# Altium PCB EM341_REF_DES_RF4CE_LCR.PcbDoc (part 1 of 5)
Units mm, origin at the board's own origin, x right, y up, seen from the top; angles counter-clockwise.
Board outline 218.38 x 83.13 mm, 2 copper layers (Top Layer, Carbon Ink Layer); 111 components, 91 nets, 369 pads, 80 vias.
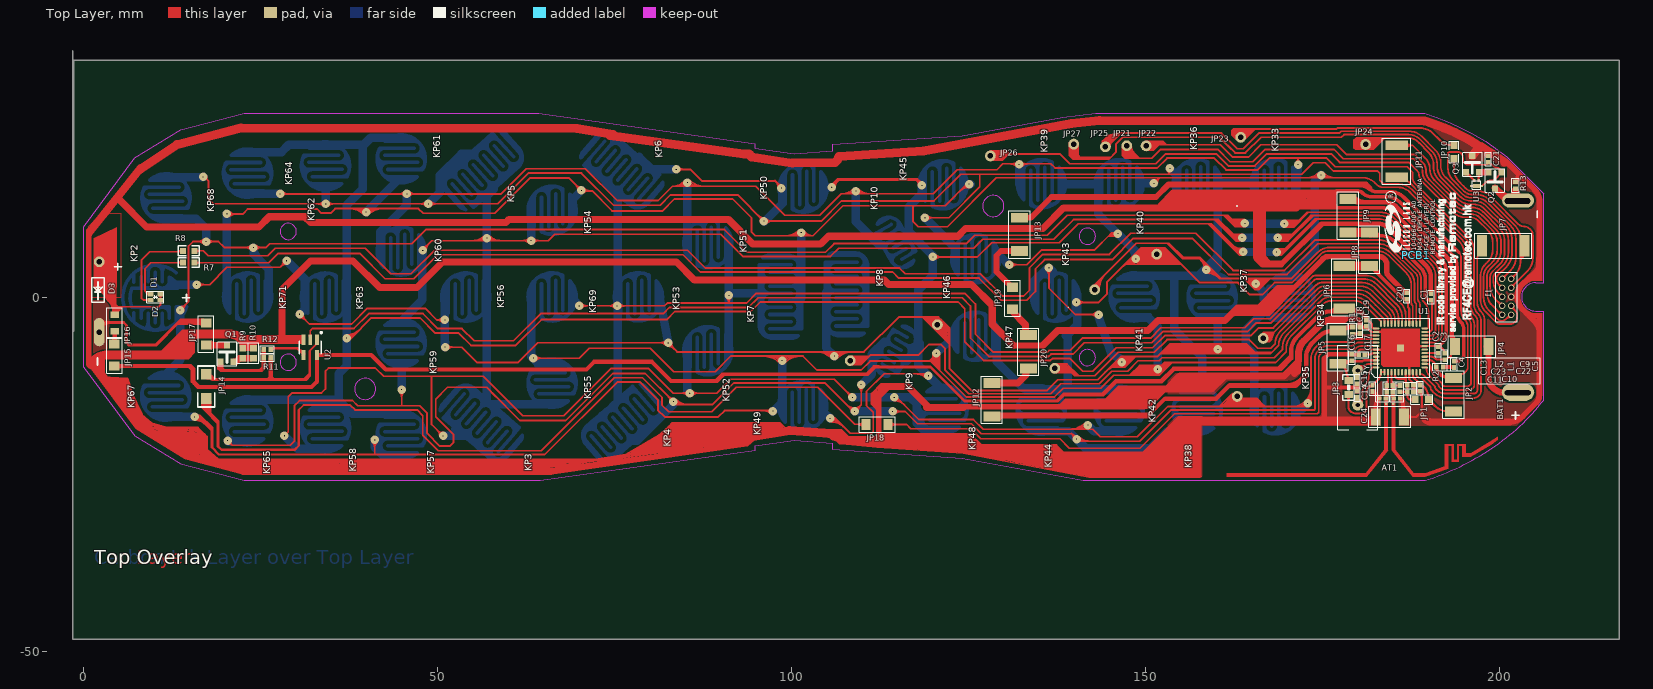
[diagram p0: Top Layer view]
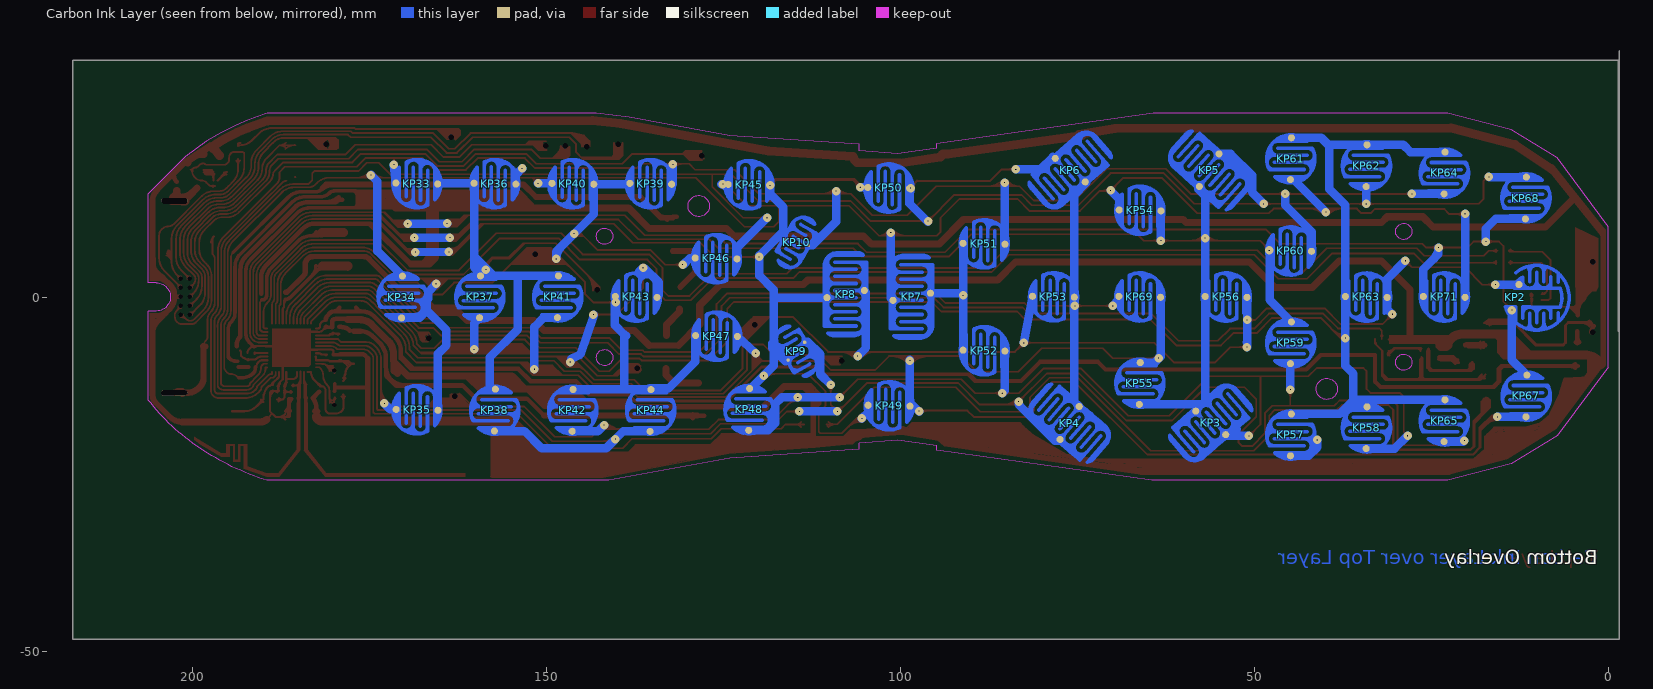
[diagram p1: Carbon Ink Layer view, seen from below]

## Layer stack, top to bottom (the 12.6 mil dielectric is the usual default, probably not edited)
Top Solder: solder mask 0.0102, Solder Resist, Dk 3.5
Top Layer: signal copper 0.0356
Dielectric1: core 0.32, FR-1 Phenolic Paper, Dk 2.7
Carbon Ink Layer: signal copper (thickness not stored)
Bottom Solder: solder mask 0.32, FR-4, Dk 4.8

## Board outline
-1.525,34.775 -1.525,-48.35 216.85,-48.35 216.85,33.425 -1.425,33.425 -1.425,-4.85

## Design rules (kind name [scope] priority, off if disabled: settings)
Clearance [All] p1: gap=0.3
FabricationTestPointUsage TestPointUsage [All] p1: valid=0 allowmultiple=FALSE
FabricationTestpoint Testpoint [(IsPad And (OnTopLayer Or OnBottomLayer))] p1: side=3 testpointundercomponent=TRUE minsize=1.016 maxsize=2.54 preferedsize=1.524 minholesize=0 maxholesize=1.016 preferedholesize=0.813 testpointgrid=0.025 allowsidetop=TRUE allowsidebottom=TRUE usegrid=TRUE gridtolerance=0
HoleSize [All] p1: absolutevalues=TRUE maxlimit=2.54 minlimit=0 maxpercent=80.000 minpercent=20.000
PlaneConnect [All] p1: planeconnectstyle=Direct reliefexpansion=0.508 reliefentries=4 reliefconductorwidth=0.254 reliefairgap=0.254
PolygonConnect [All] p1: connectstyle=Direct reliefconductorwidth=0.254 reliefentries=4 polygonreliefangle="90 Angle" airgapwidth=0.254
RoutingVias [All] p1: holewidth=0 width=1.2 viastyle="Through Hole" minholewidth=0 minwidth=1.2 maxholewidth=0 maxwidth=1.2
SolderMaskExpansion [All] p1: expansion=0.102
Width Width_1 [All] p1: maxlimit=2 minlimit=0.2 preferedwidth=0.5
25 further rules are at their usual default settings.

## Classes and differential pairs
net class JP36_Nets: PC4_2 PC4_3
net class JP35_Nets: PC4_1 PC4_2
net class JP34_Nets: PC2_1 PC2_2
net class JP25_Nets: PC0 PC0_3
net class JP23_Nets: PC0_1 PC0_5
net class JP21_Nets: JCLK JCLK_1
net class JP20_Nets: JCLK_1 JCLK_2
net class J4_Nets: JCLK_2 JCLK_3
net class J3_Nets: VDD_1 VDD_5
net class J2_Nets: VDD_1 VDD_2
net class JP11_Nets: VDD_2 VDD_7
net class JP16_Nets: PA4 PA4_1
net class JP12_Nets: PA5 PA5_1
net class JP8_Nets: NETD3_K NetJP8_2
net class JP7_Nets: VDD VDD_8
component class "PCB Only": PCB1
net class AT1_Nets: NETAT1_1 RF_N RF_P
net class BAT1_Nets: BATT_NEG VDD
net class C1_Nets: GND VDD_3
net class C2_Nets: GND NetC2_1
net class C3_Nets: GND VDD_4
net class C4_Nets: GND NetC4_1
net class C5_Nets: 1V8 GND
net class C9_Nets: 1V8_3 GND
net class C11_Nets: GND RF_P
net class C10_Nets: GND RF_N
net class C13_Nets: 1V8_1 GND
net class C14_Nets: GND OSCA
net class C15_Nets: GND OSCB
net class C16_Nets: 1V8_2 GND
net class C17_Nets: GND NetC17_1
net class C18_Nets: 1V8_39 GND
net class C19_Nets: GND VDD_5
net class C20_Nets: GND VDD_6
net class C21_Nets: GND VDD_8
net class D1_Nets: NETD1_K VDD_7
net class D2_Nets: NETD2_K VDD_7
net class D3_Nets: NETD3_K VDD_2
net class J1_Nets: GND JCLK NRESET_1 PA4_2 PA5_2 PC0_4 PC2_3 PC3_2 PC4_3 VDD_8
net class JP1_Nets: PC0_3 PC0_4
net class JP2_Nets: 1V8 1V8_3
net class JP3_Nets: VDD_3 VDD_4
net class JP5_Nets: PB6 PB6_1
net class JP6_Nets: PA5_1 PA5_2
net class JP9_Nets: 1V8 1V8_4
net class JP10_Nets: 1V8_2 1V8_5
net class JP27_Nets: NRESET NRESET_1
net class JP13_Nets: VDD VDD_4
net class JP14_Nets: 1V8_5 NetJP14_1
net class JP15_Nets: VDD_3 VDD_6
net class JP17_Nets: VDD_5 VDD_6
net class JP18_Nets: PA4_1 PA4_2
net class JP19_Nets: PC4 PC4_1
net class JP22_Nets: PC0_1 PC0_2
net class JP24_Nets: PC2 PC2_1
net class JP26_Nets: PC2_2 PC2_3
net class JP31_Nets: 1V8_1 1V8_2
net class K3_Nets: PA3 PC5
net class K4_Nets: PC2 PC5
net class K6_Nets: PC3 PC5
net class K7_Nets: PA1 PC5
net class K8_Nets: PA6 PB4
net class K9_Nets: PB2 PB4
net class K10_Nets: PA3 PB4
net class K11_Nets: PB4 PC2_3
net class K12_Nets: PA2 PB4
net class K13_Nets: PB4 PC3
net class K14_Nets: PA1 PB4
net class K15_Nets: PA0 PA6
net class K16_Nets: PA0 PB2
net class K17_Nets: PA0 PA3
net class K18_Nets: PA0 PC2
net class K19_Nets: PA0 PA2
net class K20_Nets: PA0 PC3
net class K21_Nets: PA0 PA1
net class K22_Nets: PA6 PC4
net class K23_Nets: PB2 PC4
net class K24_Nets: PA3 PC4
net class K25_Nets: PC2 PC4
net class K26_Nets: PA2 PC4
net class K27_Nets: PC3 PC4
net class K28_Nets: PA1 PC4_3
net class K29_Nets: PA6 PB0
net class K30_Nets: PB0 PB2
net class K31_Nets: PA3 PB0
net class K32_Nets: PB0 PC2
net class K33_Nets: PA2 PB0
net class K34_Nets: PB0 PC3
net class K35_Nets: PA1 PB0
net class K36_Nets: PA6 PC0
net class K37_Nets: PB2 PC0
net class K38_Nets: PA3 PC0
net class K39_Nets: PC0 PC2
net class K40_Nets: PA2 PC0
net class K41_Nets: PC0 PC3
net class K42_Nets: PA1 PC0
net class K43_Nets: PA6 PB7
net class K44_Nets: PB2 PB7
net class K45_Nets: PA3 PB7
net class K46_Nets: PB7 PC2
net class K47_Nets: PA2 PB7
net class K48_Nets: PB7 PC3
net class K49_Nets: PA1 PB7
net class L1_Nets: 1V8_3 RF_N
net class L2_Nets: RF_N RF_P
net class Q1_Nets: NETD3_K NetJP8_2 NETQ1_1 NETQ1_3
net class Q2_Nets: BATT_NEG NETQ2_S VDD_8
net class Q3_Nets: GND NETQ2_S NetQ3_1
net class R1_Nets: 1V8_5 1V8_39
net class R2_Nets: 1V8_4 NetC4_1
net class R7_Nets: NETD1_K PC7
net class R8_Nets: NETD2_K PC6
net class R9_Nets: GND NETQ1_3
net class R10_Nets: GND NETQ1_3
net class R11_Nets: NETQ1_1 PB6
net class R12_Nets: NETQ1_1 NetR12_2
net class R13_Nets: BATT_NEG GND
net class U1_Nets: 1V8 1V8_1 1V8_2 1V8_3 1V8_4 1V8_39 GND JCLK_3 NetC2_1 NetC17_1 NRESET OSCA OSCB PA0_1 PA1_1 PA2 PA3 PA4 PA5 PA6 PA7 PB0 PB1 PB2 PB4_1 PB6_1 PB7 PC0_2 PC2 PC3 PC4 PC5 PC6 PC7 RF_N RF_P TX_ALT_N TX_ALT_P VDD_3 VDD_4 VDD_5 VDD_6
net class U2_Nets: GND NetR12_2 PB1 PB6 VDD_5
net class U3_Nets: NETQ2_S NetQ3_1 VDD_8
net class Y1_Nets: OSCA OSCB
net class C22_Nets: 1V8_3 GND
net class C23_Nets: RF_N RF_P
net class C24_Nets: GND
net class JP28_Nets: PA0 PA0_1
net class JP29_Nets: PA1 PA1_1
net class JP30_Nets: PB4 PB4_1
net class JP32_Nets: NetJP14_1 NetJP32_1
net class JP33_Nets: 1V8_4 NetJP32_1
net class TP1_Nets: PC3
net class TP4_Nets: PC3_2
net class JP4_Nets: PC0 PC0_5

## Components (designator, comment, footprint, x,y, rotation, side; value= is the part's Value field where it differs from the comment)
AT1 "Dipole, RF4CE Remote" Dipole_RF4CE_Remote_1-Layer 184.45,-19.9 r270 top locked
BAT1 "BATTERY" Key-S 204.777,-9.016 r90 top locked
C1 "0.1uF" C_0402#1 190.255,-0.433 r0 top
C2 "1.0uF" C_0402#1 191.302,-7.92 r0 top
C3 "0.1uF" C_0402#1 192.202,-8.828 r0 top
C4 "2.2uF" C_0402#1 193.53,-9.942 r0 top
C5 "10NF" C_0402#1 188.745,-12.422 r180 top
C9 "2.4 pF" C_0402#1 186.897,-12.472 r270 top
C10 "1.2pF" C_0402#2 185.026,-14.34 r270 top
C11 "1.2pF" C_0402#2 183.874,-14.342 r90 top
C13 "10NF" C_0402#1 182.027,-12.442 r180 top
C14 "22PF" C_0402#3 179.857,-14.185 r0 top
C15 "22PF" C_0402#3 179.857,-11.382 r180 top
C16 "10pF" C_0402#1 179.098,-9.005 r0 top
C17 "10NF" C_0402#1 180.947,-8.145 r90 top
C18 "0.47uF" C_0402#1 180.212,-5.142 r0 top
C19 "0.1uF" C_0402#1 181.115,-3.235 r180 top
C20 "0.1uF" C_0402#1 186.84,-0.288 r0 top
C21 "0.1uF" C_0402#1 198.356,19.057 r0 top
C22 "10pF" C_0402#4 186.897,-13.374 r270 top
C23 "0.5pF" C_0402#4 183.997,-13.436 r270 top
C24 "12pF" C_ANT_JU 186.434,-16.914 r180 top
D1 "RED-LED" 2_LED 10.15,0 r90 top locked
D2 "Green-LED" 0805-L#1 10.16,0 r180 top locked
D3 "SLE2311" 0805-L#2 2.032,1.016 r270 top locked
J1 "FTSH-105-01-F-DV-K, (DNI)" "2*5 PIN_1.27MM" 200.95,0.025 r90 top locked
JP1 "Comment" L_0603_JU#1 189.93,-14.473 r270 top
JP2 "Comment" R_2010_JU#1 193.452,-11.442 r270 top
JP3 "Comment" 0805-R 178.643,-12.77 r270 top
JP4 "Comment" R_2010_JU#1 198.382,-6.983 r180 top
JP5 "Comment" R_2010_JU#1 177.12,-9.415 r90 top
JP6 "Comment" R_2512_JU 178.018,4.393 r270 top
JP7 "Comment" R_2512_JU 203.473,7.243 r180 top
JP8 "Comment" R_2010_JU#1 181.565,4.393 r90 top
JP9 "Comment" R_2010_JU#1 178.553,9.138 r90 top
JP10 "Comment" L_0603_JU#2 193.514,21.43 r0 top
JP11 "TraceJumper_1812" R_1812_JU 185.42,16.93 r90 top (schematic designator JP27)
JP12 "Comment" R_2010_JU#2 128.25,-16.85 r90 top
JP13 "Comment" R_2010_JU#1 132.15,6.5 r90 top
JP14 "Comment" 1206 17.31,-14.32 r90 top
JP15 "TraceJumper_1206" R_1206_JU 4.343,-9.745 r90 top (schematic designator J3)
JP16 "TraceJumper_0805" R_0805_JU 4.365,-4.812 r90 top (schematic designator J2)
JP17 "Comment" R_1206_JU 17.3,-3.662 r270 top (schematic designator JP8)
JP18 "TraceJumper_1206" R_1206_JU 113.6,-18 r180 top (schematic designator J3)
JP19 "TraceJumper_1206" R_1206_JU 131.175,-1.725 r90 top (schematic designator J3)
JP20 "Comment" R_2010_JU#1 133.4,-10.075 r90 top
KP2 "K7" "PCBComponent_1 - duplicate" 10.11,-0.07 r90 bottom
KP3 "K46" Key_Pad_1 56.19,-17.78 r319 bottom
KP4 "K48" Key_Pad_1 76.07,-17.82 r221 bottom
KP5 "K12" Key_Pad_1 56.37,17.88 r222 bottom
KP6 "K14" Key_Pad_1 76.03,17.92 r319 bottom
KP7 "K37" Key_Pad_1 98.4,0.01 r270 bottom
KP8 "K39" Key_Pad_1 107.73,0.39 r270 bottom
KP9 "K29" Key_Pad_2 114.53,-7.56 r240 bottom
KP10 "K38" Key_Pad_2 114.79,7.79 r120 bottom
KP33 "K21" KEY-7 168.25,16.02 r180 bottom
KP34 "K16" KEY-7 170.35,0.03 r90 bottom
KP35 "K23" KEY-7 168.26,-15.91 r0 bottom
KP36 "K19" KEY-7 157.26,16.02 r0 bottom
KP37 "K18" KEY-7 159.36,0.01 r270 bottom
KP38 "K25" KEY-7 157.26,-15.99 r270 bottom
KP39 "K15" KEY-7 135.26,16.01 r0 bottom
KP40 "K17" KEY-7 146.25,16.01 r0 bottom
KP41 "K20" KEY-7 148.36,0.02 r270 bottom
KP42 "K27" KEY-7 146.25,-15.98 r90 bottom
KP43 "K32" KEY-7 137.26,0 r180 bottom
KP44 "K34" KEY-7 135.25,-15.99 r90 bottom
KP45 "K35" KEY-7 121.37,15.86 r0 bottom
KP46 "K33" KEY-7 125.98,5.43 r180 bottom
KP47 "K31" KEY-7 125.92,-5.52 r180 bottom
KP48 "K30" KEY-7 121.35,-15.89 r270 bottom
KP49 "K41" KEY-7 101.56,-15.36 r180 bottom
KP50 "K40" KEY-7 101.61,15.4 r180 bottom
KP51 "K42" KEY-7 88.15,7.51 r180 bottom
KP52 "K36" KEY-7 88.15,-7.58 r180 bottom
KP53 "K43" KEY-7 78.35,0.03 r180 bottom
KP54 "K49" KEY-7 66.16,12.25 r0 bottom
KP55 "K44" KEY-7 66.16,-12.18 r90 bottom
KP56 "K47" KEY-7 53.96,0.01 r180 bottom
KP57 "K22" KEY-7 44.85,-19.49 r270 bottom
KP58 "K24" KEY-7 34.16,-18.48 r270 bottom
KP59 "K9" KEY-7 44.85,-6.48 r270 bottom
KP60 "K8" KEY-7 44.85,6.51 r180 bottom
KP61 "K10" KEY-7 44.85,19.51 r270 bottom
KP62 "K11" KEY-7 34.16,18.52 r270 bottom
KP63 "K13" KEY-7 34.16,0 r180 bottom
KP64 "K3" KEY-7 23.15,17.5 r270 bottom
KP65 "K6" KEY-7 23.16,-17.49 r270 bottom
KP67 "K4" KEY-7 11.59,-13.99 r270 bottom
KP68 "K28" KEY-7 11.64,14.01 r90 bottom
KP69 "K45" KEY-7 66.16,0.02 r180 bottom
KP71 "K26" KEY-7 23.16,0.01 r180 bottom
L1 "22nH" L_0402 185.898,-12.489 r270 top
L2 "3.3nH" L_0402 184.9,-12.484 r180 top
PCB1 "EM341/RF4CE Lattice Balun 1 Layer Remote Prototype Corporate Logo" 710-0664-004 188.175,5.875 r90 top
Q1 "8050D" SMDPN 19.304,-9.144 r0 top
Q2 "AO3434A" SMDPN 200.26,17.625 r180 top
Q3 "AO3434A" SMDPN 195.174,17.62 r0 top
R1 "10 Ohm" R_0402#1 179.205,-4.225 r270 top
R2 "1 Ohm" R_0402#1 191.03,-9.881 r0 top
R7 "Comment" 0603 15.65,4.88 r180 top
R8 "" 0603 15.65,6.53 r180 top
R9 "6.8R" R_0603 22.475,-7.925 r270 top
R10 "6.8R" R_0603 24,-7.925 r270 top
R11 "470R" R_0402#2 25.425,-8.55 r0 top
R12 "DNI" R_0402#2 25.417,-7.403 r0 top
R13 "DNI" R_0402#1 202.197,16.279 r270 top
U1 "EM341" EM357_RF4CE_GND_GPIO 185.953,-7.175 r270 top locked
U2 "NC7SZ08M5X" SOT23-5 32.004,-7.112 r180 top
U3 "Supervisor" USP-3 196.698,15.915 r0 top
Y1 "24.000MHZ, 18PF LOAD" HC-49-TH 179.93,-12.79 r90 top

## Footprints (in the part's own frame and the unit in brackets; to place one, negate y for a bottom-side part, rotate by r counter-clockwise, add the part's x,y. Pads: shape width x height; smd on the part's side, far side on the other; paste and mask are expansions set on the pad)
"2*5 PIN_1.27MM" [mm]
  round 0.9 / inner round 0.9 / far side round 0 hole 0.65: 1(2.54,-0.635) 2(2.54,0.635) 3(1.27,-0.635) 4(1.27,0.635) 5(0,-0.635) 6(0,0.635) 7(-1.27,-0.635) 8(-1.27,0.635) 9(-2.54,-0.635) 10(-2.54,0.635)
  silkscreen extent -3.5,-1.5 3.5,1.5
2_LED [mm]
  rect 0.6x0.8 smd: 1(0.4,-0.7) 2(0.4,0.7) 3(-0.4,0.7) 4(-0.4,-0.7)
  silkscreen extent -0.8,-1.2 0.8,1.23
0603 [mil]
  rect 33x33 smd: 1(0,0) 2(62.99,0)
  silkscreen extent -28,-28 91,28
710-0664-004 [mm] "EM35x/RF4CE Dipole Layer Remote Prototype"
  silkscreen extent 0.12,0.89 9.01,4.38
0805-L#1 [mm]
  rect 0.8x0.6 smd: 1(-0.69,0.4) 2(0.71,0.4)
0805-L#2 [mm]
  round 1.524 smd: 2(5.966,0.168)
  silkscreen extent -1.71,-0.86 1.74,0.87
0805-R [mm]
  rect 1x1.2 smd: 1(-1,-0.007) 2(1,-0.007)
  silkscreen extent -1.79,-0.83 1.79,0.81
1206 [mil]
  rect 60x60 smd: 1(0,0) 2(135,0)
  silkscreen extent -47,-47 181,47
C_0402#1 [mm]
  rect 0.6x0.65 smd mask+0.03: 1(0,0) 2(0,0.9)
  silkscreen extent -0.45,-0.5 0.45,1.4
C_0402#2 [mm]
  rect 0.6x0.65 smd mask+0.03: 1(0,0)
  rect 0.6x0.65 smd mask+0: 2(0,0.9)
  silkscreen extent -0.45,-0.5 0.45,1.4
C_0402#3 [mm]
  rect 0.6x0.65 smd: 1(0,0)
  rect 0.6x0.65 smd mask+0: 2(0,0.9)
  silkscreen extent -0.45,-0.5 0.45,1.4
C_0402#4 [mm]
  rect 0.6x0.65 smd mask+0.051: 1(0,0) 2(0,0.9)
  silkscreen extent -0.45,-0.5 0.45,1.4, body extent -0.28,-0.05 0.28,0.97, height 1.02
C_ANT_JU [mm] "1206 Capacitor Special for Dipole Ant"
  rect 1.4x2.4 smd: 1(0,0) 2(3.962,0)
  silkscreen extent -1,-1.5 4.98,1.5, body extent -0.15,-1.25 4.14,1.25, height 1.02
Dipole_RF4CE_Remote_1-Layer [mm] "Dipole for Remote Reference Design"
  rect 0.35x0.35 smd mask+0.05: 1(-4.808,-0.5) 2(-4.808,0.5)
  Top Layer region: 2.666,10.752 0.86,10.752 1.11,10.252 2.666,10.252
  Top Layer region: 3.36,9.752 1.11,9.752 0.86,9.502 3.11,9.502
  Top Layer region: 2.664,11.449 0.952,14.313 0.267,15.265 -0.192,15.265 0.533,14.097 2.162,11.411
  Top Layer region: 2.664,10.752 2.664,11.449 2.162,11.411 2.164,10.752
  Top Layer region: 1.11,9.752 1.11,10.252 0.86,10.752 0.86,9.502
  Top Layer region: 3.36,8.752 3.36,9.752 3.11,9.502 3.11,9.002
  Top Layer region: 3.11,9.002 0.86,9.002 1.11,8.752 3.36,8.752
  Top Layer region: 5.503,5.002 4.332,8.252 3.994,7.752 5.003,5.002
  Top Layer pour cut-out: 5.977,18.593 5.977,-26.5 -1.747,-26.5 -1.747,-1.25 -5.5,-1.25 -5.5,1.249 -1.747,1.251 -1.747,18.593
  Top Layer region: 1.671,-0.748 5.003,-3.413 5.503,-3.248 1.753,-0.248
  Top Layer region: 5.503,-22.998 5.503,-3.248 5.003,-3.413 5.003,-22.998
  Top Layer region: 5.503,3.252 5.503,5.002 5.003,5.002 5.003,3.414
  Top Layer region: 4.332,8.252 1.11,8.252 0.86,7.752 3.994,7.752
  Top Layer region: 1.753,0.252 5.503,3.252 5.003,3.414 1.675,0.752
  Top Layer region: -5,0.25 1.753,0.25 1.675,0.752 -5,0.75
  Top Layer region: -5,-0.75 1.671,-0.748 1.753,-0.25 -5,-0.25
  Top Layer region: 1.11,8.252 1.11,8.752 0.86,9.002 0.86,7.752
  Multi-Layer pour cut-out: 5.977,18.593 -1.755,18.593 -1.755,1.25 -5.5,1.25 -5.5,-1.25 -1.755,-1.25 -1.755,-26.5 5.977,-26.5
EM357_RF4CE_GND_GPIO [mm] "Grounded GPIOs"
  oval 0.9x0.3 smd paste+0 mask+0: 1(3.425,-2.75) 2(3.425,-2.25) 3(3.425,-1.75) 4(3.425,-1.25) 5(3.425,-0.75) 6(3.425,-0.25) 7(3.425,0.25) 8(3.425,0.75) 9(3.425,1.25) 10(3.425,1.75) 11(3.425,2.25) 12(3.425,2.75) 25(-3.425,2.75) 26(-3.425,2.25) 27(-3.425,1.75) 28(-3.425,1.25) 29(-3.425,0.75) 30(-3.425,0.25) 31(-3.425,-0.25) 32(-3.425,-0.75) 33(-3.425,-1.25) 34(-3.425,-1.75) 35(-3.425,-2.25) 36(-3.425,-2.75)
  oval 0.3x0.9 smd paste+0 mask+0: 13(2.75,3.425) 14(2.25,3.425) 15(1.75,3.425) 16(1.25,3.425) 17(0.75,3.425) 18(0.25,3.425) 19(-0.25,3.425) 20(-0.75,3.425) 21(-1.25,3.425) 22(-1.75,3.425) 23(-2.25,3.425) 24(-2.75,3.425) 37(-2.75,-3.425) 38(-2.25,-3.425) 39(-1.75,-3.425) 40(-1.25,-3.425) 41(-0.75,-3.425) 42(-0.25,-3.425) 43(0.25,-3.425) 44(0.75,-3.425) 45(1.25,-3.425) 46(1.75,-3.425) 47(2.25,-3.425) 48(2.75,-3.425)
  rect 1x1 smd paste-1 mask+0: 49(0,0)
  Top Layer region: 2.477,1.4 3.609,1.4 3.609,1.101 2.477,1.101
  Top Layer region: 0.4,-2.533 0.4,-3.665 0.1,-3.665 0.1,-2.533
  Top Layer pour cut-out: -3.039,-3.503 -3.499,-3.503 -3.499,-3.043 -3.039,-3.043
  Top Layer pour cut-out: -3.039,3.04 -3.499,3.04 -3.499,3.5 -3.039,3.5
  Top Layer pour cut-out: 3.507,3.04 3.047,3.04 3.047,3.5 3.507,3.5
  Top Layer pour cut-out: 3.506,-3.505 3.046,-3.505 3.046,-3.045 3.506,-3.045
  Top Layer region: 2.7,-2.4 2.4,-2.7 -2.7,-2.7 -2.7,2.7 2.7,2.7
  Top Layer region: -0.1,3.718 -0.1,2.586 -0.4,2.586 -0.4,3.718
  Top Layer region: -2.1,-2.555 -2.1,-3.687 -2.4,-3.687 -2.4,-2.555
  silkscreen extent -4.15,-4.15 4.15,4.15, body extent -3.51,-3.51 3.51,3.51, height 0.9
HC-49-TH [mm]
  round 1.6 / inner round 1.6 / far side round 0 hole 0.584: 1(-2.438,0) 2(2.438,0)
  silkscreen extent -5.97,-2.79 5.97,2.79
KEY-7 [mm]
  round 1 smd: 1(-2.976,0.08) 2(2.927,-0.05)
  Top Layer lines w0.5: 2.508,-2.298 ccw(c0.001,-0.001) 2.705,-2.062 ccw(c0.001,-0.001) 2.85,-1.857 ccw(c0.001,-0.001) 2.875,-1.818 ccw(c0.001,-0.001) 2.9,-1.778 ccw(c0.001,-0.001) 3.075,-1.454 ccw(c0.001,-0.001) 3.308,-0.794 ccw(c0.001,-0.001) 3.401,0.018 ccw(c0.001,-0.001) 3.401,0.05 ccw(c0.001,-0.001) 3.399,0.129 ccw(c0.001,-0.001) 3.395,0.21 ccw(c0.001,-0.001) 3.343,0.625 ccw(c0.001,-0.001) 3.306,0.8 ccw(c0.001,-0.001) 3.295,0.843 ccw(c0.001,-0.001) 3.265,0.954 ccw(c0.001,-0.001) 3.251,1 ccw(c0.001,-0.001) 3.192,1.175 ccw(c0.001,-0.001) 2.975,1.648 ccw(c0.001,-0.001) 2.945,1.7 ccw(c0.001,-0.001) 2.875,1.817 ccw(c0.001,-0.001) 2.45,2.358 ccw(c0.001,-0.001) 2.21,2.585 ; 2.5,-2.29 2.5,-1.225 2.5,-0.175 2.5,-0.15 2.5,0.05 2.5,0.1 2.5,0.125 2.5,0.21 2.5,0.544 2.5,0.8 2.5,0.954 2.5,0.972 2.5,1 2.5,1.175 2.5,1.7 2.5,1.88 ; 2.5,2.289 2.5,2.162 2.5,1.88 ; 1.5,-2.994 1.5,-2.35 ; 1.5,1.88 1.5,-2.35 ; 1.494,-3.054 cw(c0,0) 1.464,-3.069 cw(c0,0) 0.791,-3.307 ; 0.5,-2.35 0.5,0.8 0.5,0.954 0.5,1.125 0.5,1.225 0.5,1.321 0.5,1.435 0.5,1.7 0.5,1.88 ; 0.5,2.824 0.5,2.342 ; -0.5,-2.826 -0.5,-2.352 ; -0.5,2.34 -0.5,1.6 -0.5,-0.875 -0.5,-1.25 -0.5,-1.41 -0.5,-1.525 -0.5,-1.544 -0.5,-1.725 -0.5,-1.86 ; -1.421,3.088 cw(c0.001,-0.001) -1.328,3.128 cw(c0.001,-0.001) 0.046,3.399 cw(c0.001,-0.001) 0.128,3.397 cw(c0.001,-0.001) 0.28,3.388 cw(c0.001,-0.001) 0.534,3.357 cw(c0.001,-0.001) 0.617,3.343 cw(c0.001,-0.001) 0.65,3.337 cw(c0.001,-0.001) 1.054,3.232 cw(c0.001,-0.001) 1.694,2.948 cw(c0.001,-0.001) 2.028,2.729 ; -1.5,-1.86 -1.5,-1 -1.5,-0.95 -1.5,-0.25 -1.5,0.8 -1.5,1.175 -1.5,2.34 ; -1.5,3.036 -1.5,2.34 ; -2.5,-2.253 -2.5,-1.863 ; -2.5,2.289 -2.5,1.58 -2.5,-0.075 -2.5,-0.29 -2.5,-0.499 -2.5,-0.875 -2.5,-1.41 -2.5,-1.456 -2.5,-1.761 -2.5,-1.85 -2.5,-1.86 ; -2.507,2.296 ccw(c0,0) -3.025,1.552 ccw(c0,0) -3.112,1.369 ccw(c0,0) -3.206,1.133 ccw(c0,0) -3.376,0.4 ccw(c0,0) -3.4,0.05 ccw(c0,0) -3.398,-0.121 ccw(c0,0) -3.371,-0.446 ccw(c0,0) -3.285,-0.875 ccw(c0,0) -3.094,-1.41 ccw(c0,0) -2.888,-1.794 ccw(c0,0) -2.86,-1.839 ccw(c0,0) -2.276,-2.526 ccw(c0,0) -2.011,-2.741 ccw(c0,0) -1.836,-2.861 ccw(c0,0) -1.552,-3.025 ccw(c0,0) -1.502,-3.05 ccw(c0,0) -1.367,-3.113 ccw(c0,0) -1.01,-3.246 ccw(c0,0) -0.961,-3.261 ccw(c0,0) -0.838,-3.295 ccw(c0,0) -0.824,-3.299 ccw(c0,0) -0.57,-3.352 ccw(c0,0) -0.55,-3.355 ccw(c0,0) -0.392,-3.377 ccw(c0,0) -0.26,-3.39 ccw(c0,0) 0.1,-3.399 ccw(c0,0) 0.152,-3.397 ccw(c0,0) 0.2,-3.394 ccw(c0,0) 0.475,-3.367 ccw(c0,0) 0.483,-3.366 ccw(c0,0) 0.623,-3.342 ; 2.5,1.88 ccw(c1.5,1.88) 2.21,2.585 ; 2.21,2.585 ccw(c0.001,-0.001) 2.161,2.625 ccw(c0.001,-0.001) 2.045,2.717 ccw(c0.001,-0.001) 2.029,2.729 ; 2.21,2.585 ccw(c1.5,1.88) 2.163,2.628 ccw(c1.5,1.88) 2.045,2.718 ccw(c1.5,1.88) 2.028,2.729 ; 2.028,2.729 ccw(c1.5,1.88) 0.5,1.88 ; 1.5,-2.35 cw(c0.5,-2.35) 0.791,-3.307 ; 0.791,-3.307 cw(c0.5,-2.35) 0.623,-3.342 ; 0.791,-3.307 cw(c0,0) 0.623,-3.342 ; 0.623,-3.342 cw(c0.5,-2.35) 0.481,-3.35 cw(c0.5,-2.35) 0.475,-3.35 cw(c0.5,-2.35) 0.2,-3.304 cw(c0.5,-2.35) 0.1,-3.267 cw(c0.5,-2.35) -0.5,-2.352 ; 0.5,1.88 0.5,2.34 ; 0.5,2.34 ccw(c-0.5,2.34) 0.5,2.342 ; 0.5,2.34 0.5,2.342 ; 0.5,2.342 ccw(c-0.5,2.34) 0.28,2.966 ccw(c-0.5,2.34) -1.5,2.34 ; -0.5,-2.352 cw(c0.5,-2.35) -0.5,-2.35 ; -0.5,-2.352 -0.5,-2.35 ; -0.5,-2.35 -0.5,-1.86 ; -0.5,-1.86 cw(c-1.5,-1.86) -1.792,-2.817 cw(c-1.5,-1.86) -2.073,-2.68 cw(c-1.5,-1.86) -2.26,-2.51 cw(c-1.5,-1.86) -2.32,-2.433 cw(c-1.5,-1.86) -2.5,-1.863 ; -2.5,-1.863 cw(c-1.5,-1.86) -2.5,-1.86 ; -2.5,-1.863 -2.5,-1.86
  Top Layer lines w0.6: 3.17,-0.46 3.17,-0.157 3.17,0 3.17,0.018 3.17,0.025 3.17,0.05 3.17,0.1 3.17,0.21 3.17,0.225 3.17,0.544 3.17,0.625 3.17,0.72 ; 2.8,-1.53 2.8,-1.225 2.8,-0.175 2.8,-0.15 2.8,0 2.8,0.025 2.8,0.05 2.8,0.1 2.8,0.21 2.8,0.544 2.8,0.596 2.8,0.625 2.8,0.8 2.8,0.954 2.8,1 2.8,1.175 2.8,1.338 2.8,1.59 ; 0.816,2.839 0.708,2.948 0.628,3.028 0.59,3.065 0.549,3.106 0.424,3.232 0.345,3.232 ; -0.637,-3.092 -0.665,-3.065 -0.677,-3.052 -0.679,-3.05 -0.702,-3.027 -0.704,-3.025 -0.715,-3.015 -0.873,-2.856 -0.925,-2.856 -0.941,-2.856 ; -2.79,-1.45 -2.79,-1.41 -2.79,-0.875 -2.79,-0.499 -2.79,-0.29 -2.79,-0.1 -2.79,-0.075 -2.79,0.05 -2.79,0.4 -2.79,0.475 -2.79,1.511 -2.79,1.75 ; -3.16,-0.6 -3.16,-0.499 -3.16,-0.235 -3.16,-0.2 -3.16,-0.15 -3.16,-0.1 -3.16,-0.075 -3.16,0.05 -3.16,0.4 -3.16,0.475 -3.16,0.81
Key-S [mm]
  oval 2.4x4.6 smd: 1(-4.44,2.221)
  oval 2x4.5 smd: 2(22.648,2.21)
Key_Pad_1 [mm]
  round 1 smd: 1(-0.535,2.661) 2(0.476,-2.626)
  Top Layer lines w0.4: -4.524,2.656 -2.524,2.658 -0.535,2.661 -0.35,2.661 -0.225,2.661 0.282,2.662 1.476,2.663 1.575,2.663 3.2,2.665 3.476,2.666 3.6,2.666 3.65,2.666 4.996,2.667 ; -4.978,-2.629 -3.524,-2.628 -1.524,-2.627 -0.05,-2.626 0.05,-2.626 0.1,-2.626 0.145,-2.626 0.476,-2.626 2.425,-2.624 2.476,-2.624 2.55,-2.624 4.473,-2.623
  Top Layer lines w0.5: -5.52,2.501 -5.522,1.1 -5.523,0.225 -5.524,-1.499 ; -2.524,3.001 -2.524,3.001 ; -5.837,-1.115 ccw(c-3.937,-1.11) -4.27,-2.981 ccw(c-3.937,-1.11) -4.164,-2.997 ; -3.524,1.501 -3.524,-1.499 ; -4.524,-1.499 -4.524,1.501 ; -0.535,3.001 -0.535,3 ; -1.524,1.501 -1.524,-1.647 ; -3.932,-3.01 cw(c-3.937,-1.11) -4.164,-2.997 ; -2.524,-1.499 -2.524,1.501 ; 1.476,3.001 1.476,3 ; -3.524,-2.999 -3.524,-2.628 -3.524,-1.501 ; 0.476,1.501 0.476,-2.626 0.476,-2.725 0.476,-2.825 0.476,-2.999 ; -1.535,-1.499 ccw(c-0.535,-1.499) -1.53,-1.604 ; -1.524,-1.499 cw(c-2.524,-1.499) -1.53,-1.604 ; -0.535,-1.499 -0.535,1.65 ; 3.476,3.001 3.476,2.999 ; -1.524,-2.999 -1.524,-2.627 -1.524,-1.647 ; 2.476,1.501 2.476,-1.502 ; 3.865,2.999 3.65,2.999 3.6,2.999 3.476,2.999 ; 3.928,3.008 cw(c3.932,1.108) 4.438,2.94 cw(c3.932,1.108) 4.488,2.925 cw(c3.932,1.108) 4.844,2.775 cw(c3.932,1.108) 5.076,2.625 cw(c3.932,1.108) 5.832,1.113 5.832,-1.64 cw(c4.617,-1.64) 5.476,-2.499 5.476,1.501 ccw(c4.476,1.501) 3.476,1.501 ; 0.465,-1.499 cw(c-0.535,-1.499) 0.035,-2.32 cw(c-0.535,-1.499) -1.524,-1.647 ; 0.476,-1.499 ccw(c1.476,-1.499) 2.476,-1.502 ; 1.476,-1.499 1.476,1.504 ; 4.476,1.501 4.476,-1.499 ; 3.476,-1.499 3.476,1.501 ; 2.476,-2.999 2.476,-2.9 2.476,-2.725 2.476,-2.624 2.476,-1.502 ; -4.524,1.501 cw(c-3.524,1.501) -2.524,1.504 ; -4.524,1.501 -4.524,2.656 -4.524,3.001 -2.524,3.001 ; -2.524,3.001 -0.535,3 ; -2.524,3.001 -2.524,2.658 -2.524,1.504 ; -5.524,-1.499 ccw(c-4.524,-1.499) -3.524,-1.501 ; -5.524,-1.499 -5.525,0.225 -5.525,1.1 -5.525,2.501 ccw(c-4.666,1.642) -5.7,2.28 ccw(c-4.666,1.642) -5.775,2.139 ccw(c-4.666,1.642) -5.881,1.642 -5.881,1.1 -5.881,0.225 -5.881,-1.11 ccw(c-3.981,-1.106) -4.267,-2.984 ccw(c-3.981,-1.106) -4.164,-2.997 ; -2.524,1.504 cw(c-1.524,1.501) -0.535,1.65 ; -2.524,1.504 ccw(c-1.524,1.501) -2.524,1.503 ; -2.524,1.504 cw(c-3.524,1.501) -2.524,1.503 ; -2.524,1.504 -2.524,1.501 ; -2.524,1.503 ccw(c-1.524,1.501) -2.524,1.501 ; -2.524,1.503 cw(c-3.524,1.501) -2.524,1.501 ; -0.535,3 -0.35,3 -0.225,3 0.531,3 1.476,3 ; -0.535,3 -0.535,2.875 -0.535,2.85 -0.535,2.661 -0.535,1.65 ; -3.524,-1.499 cw(c-4.524,-1.499) -3.524,-1.5 ; -3.524,-1.499 ccw(c-2.524,-1.499) -3.524,-1.5 ; -3.524,-1.499 -3.524,-1.501 ; -3.524,-1.5 ccw(c-2.524,-1.499) -3.524,-1.501 ; -3.524,-1.5 cw(c-4.524,-1.499) -3.524,-1.501 ; -3.524,-1.501 ccw(c-2.524,-1.499) -1.53,-1.604 ; -0.535,1.65 cw(c-1.524,1.501) -0.524,1.503 ; -0.524,1.503 cw(c0.476,1.501) 0.17,2.453 cw(c0.476,1.501) 1.476,1.504 ; -0.524,1.503 ccw(c0.476,1.501) -0.524,1.501 ccw(c-1.524,1.501) -0.524,1.503 ; -4.164,-2.997 ccw(c-3.981,-1.106) -3.976,-3.006 -0.05,-3.002 0.05,-3.002 0.1,-3.002 0.315,-3.002 0.355,-3.002 2.4,-3 2.425,-3 2.55,-3 2.657,-3 4.071,-2.999 4.427,-2.999 4.476,-2.999 4.476,-1.499 ; 1.476,3 1.575,3 1.725,3 3.2,2.999 3.476,2.999 ; 1.476,3 1.476,2.875 1.476,2.85 1.476,2.663 1.476,1.504 ; -1.53,-1.604 ccw(c-0.535,-1.499) -1.524,-1.647 ; 1.476,1.504 cw(c0.476,1.501) 1.476,1.501 cw(c2.476,1.501) 1.476,1.504 ; 1.476,1.504 cw(c2.476,1.501) 3.476,1.501 ; 3.476,2.999 3.476,2.925 3.476,2.875 3.476,2.775 3.476,2.666 3.476,2.625 3.476,1.501 ; 2.476,-1.5 ccw(c1.476,-1.499) 2.476,-1.499 ccw(c3.476,-1.499) 2.476,-1.5 ; 2.476,-1.5 cw(c1.476,-1.499) 2.476,-1.502 ; 2.476,-1.5 ccw(c3.476,-1.499) 2.476,-1.502 ; 2.476,-1.502 cw(c1.476,-1.499) 2.476,-1.502 ; 2.476,-1.502 ccw(c3.476,-1.499) 2.476,-1.502 ; 2.476,-1.502 2.476,-1.502 ; 2.476,-1.502 ccw(c3.476,-1.499) 4.476,-1.499
Key_Pad_2 [mm]
  round 0.5 smd: 1(-0.497,1.481) 2(0.503,-1.803)
  Top Layer lines w0.5: 2.456,1.627 ccw(c2.521,0.63) 1.521,0.63 ; 3.503,0.913 3.503,0.896 ; 1.503,1.614 1.503,0.761 ; 2.503,0.597 2.503,-0.975 ; 1.505,0.698 ccw(c0.505,0.698) 1.503,0.761 ; -0.497,1.614 -0.497,1.609 -0.497,1.549 -0.497,1.506 -0.497,1.484 -0.497,1.481 -0.497,1.285 -0.497,0.954 -0.497,0.756 ; 0.503,0.697 0.503,-0.977 ; -0.495,0.698 cw(c0.505,0.698) -0.455,0.978 cw(c0.505,0.698) 0.134,1.627 cw(c0.505,0.698) 0.215,1.655 cw(c0.505,0.698) 0.457,1.697 ; -0.495,0.692 ccw(c-1.495,0.692) -0.497,0.756 ; -2.491,1.697 -0.583,1.697 -0.558,1.697 -0.424,1.697 -0.412,1.697 -0.383,1.697 -0.335,1.697 -0.279,1.697 -0.168,1.697 0.089,1.697 0.152,1.697 0.204,1.697 0.457,1.697 ; -2.497,1.614 -2.497,-0.615 ; 1.503,-0.779 1.503,0.761 ; -1.499,0.697 -1.499,-0.86 ; -1.499,0.493 -1.499,-0.86 ; 0.501,-0.955 cw(c-0.499,-0.955) 0.331,-1.512 cw(c-0.499,-0.955) -0.433,-1.953 cw(c-0.499,-0.955) -1.499,-0.959 ; 0.503,-0.974 ccw(c1.503,-0.974) 0.503,-0.977 ; -2.495,0.692 cw(c-1.495,0.692) -0.526,0.937 cw(c-1.495,0.692) -0.497,0.756 ; -0.497,-0.812 -0.497,0.756 ; 0.503,-1.803 0.503,-1.413 0.503,-0.978 ; -1.499,-0.955 ccw(c-0.499,-0.955) -1.499,-0.958 ; -1.499,-0.974 cw(c-2.499,-0.974) -2.303,-1.954 ; -3.811,0.051 cw(c-2.748,0.051) -3.773,0.331 cw(c-2.748,0.051) -3.75,0.404 cw(c-2.748,0.051) -3.499,0.802 -3.499,0.327 -3.499,0.28 -3.499,-1.181 ; -3.811,-0.169 ccw(c-2.007,-0.169) -3.499,-1.181 ; -1.499,-1.803 -1.499,-1.774 ; -1.499,-1.899 -1.499,-1.876 -1.499,-1.808 -1.499,-1.774 ; -1.983,-1.979 -1.677,-1.979 -1.381,-1.979 -1.372,-1.979 -0.477,-1.979 1.142,-1.979 2.272,-1.979 2.284,-1.979 2.375,-1.979 2.503,-1.979 2.503,-1.978 2.503,-1.914 2.503,-1.896 2.503,-1.857 2.503,-1.835 2.503,-1.824 2.503,-1.703 2.503,-0.976 ; -1.983,-1.982 cw(c-1.983,-0.144) -2.303,-1.954 ; -3.499,-1.198 -3.499,-1.181 ; -2.329,-1.959 ccw(c-2.499,-0.974) -2.303,-1.954 ; 3.503,0.896 cw(c2.01,-0.117) 3.814,-0.117 3.814,-0.336 cw(c2.751,-0.336) 3.503,-1.087 3.503,0.896 ; 3.503,0.896 ccw(c2.01,-0.117) 3.286,1.159 ccw(c1.986,-0.141) 1.986,1.697 0.789,1.697 0.552,1.697 ; 0.552,1.697 ccw(c0.505,0.698) 0.457,1.697 ; 0.552,1.697 cw(c0.505,0.698) 0.742,1.669 cw(c0.505,0.698) 1.503,0.761 ; 0.552,1.697 0.552,1.697 ; 0.552,1.697 0.498,1.697 ; 0.552,1.697 0.552,1.697 ; 0.498,1.697 0.457,1.697 ; 0.498,1.697 0.498,1.697 ; 0.457,1.697 0.457,1.697 ; 0.457,1.697 0.457,1.697 ; 0.457,1.697 0.457,1.697 ; 0.457,1.697 0.457,1.697 ; 0.457,1.697 0.457,1.697 ; 0.457,1.697 0.457,1.697 ; 0.457,1.697 0.457,1.697 ; 0.457,1.697 0.457,1.697 ; 0.457,1.697 0.457,1.697 ; 0.457,1.697 0.457,1.697 ; 0.457,1.697 0.457,1.697 ; 0.457,1.697 0.457,1.697 ; 0.457,1.697 0.457,1.697 ; 0.457,1.697 0.457,1.697 ; 0.457,1.697 0.457,1.697 ; 0.457,1.697 0.457,1.697 ; 0.457,1.697 0.457,1.697 ; 0.457,1.697 0.457,1.697 ; 0.457,1.697 0.457,1.697 ; 0.457,1.697 0.457,1.697 ; 0.457,1.697 0.457,1.697 ; 0.457,1.697 0.457,1.697 ; 0.457,1.697 0.457,1.697 ; 1.503,0.761 1.503,0.761 ; 1.503,0.761 1.503,0.761 ; 1.503,0.761 1.503,0.761 ; 1.503,0.761 1.503,0.761 ; 1.503,0.761 1.503,0.761 ; 1.503,0.761 1.503,0.761 ; 1.503,0.761 1.503,0.761 ; 1.503,0.761 1.503,0.761 ; 1.503,0.761 1.503,0.761 ; 1.503,0.761 1.503,0.761 ; 1.503,0.761 1.503,0.761 ; 1.503,0.761 1.503,0.761 ; 1.503,0.761 1.503,0.761 ; 1.503,0.761 1.503,0.761 ; 1.503,0.761 1.503,0.761 ; 1.503,0.761 1.503,0.761 ; 1.503,0.761 1.503,0.761 ; 2.503,-0.975 cw(c1.503,-0.974) 2.503,-0.976 ; 2.503,-0.974 cw(c1.503,-0.974) 2.503,-0.975 ; 2.503,-0.975 2.503,-0.976 ; 2.503,-0.976 ccw(c1.503,-0.974) 2.503,-0.976 ; 2.503,-0.976 cw(c1.503,-0.974) 1.088,-1.884 cw(c1.503,-0.974) 0.583,-1.367 cw(c1.503,-0.974) 0.503,-0.978 ; 2.503,-0.976 2.503,-0.976 ; -0.497,0.756 -0.497,0.756 ; -0.497,0.756 -0.497,0.756 ; 0.503,-0.977 ccw(c1.503,-0.974) 0.503,-0.978 ; 0.503,-0.977 0.503,-0.977 ; 0.503,-0.977 0.503,-0.977 ; 0.503,-0.977 0.503,-0.977 ; 0.503,-0.977 0.503,-0.977 ; 0.503,-0.977 0.503,-0.977 ; 0.503,-0.977 0.503,-0.978 ; -1.499,-0.86 -1.499,-0.958 ; -1.499,-0.86 -1.499,-0.958 ; -1.499,-0.958 ccw(c-0.499,-0.955) -1.499,-0.959 ; -1.499,-0.958 -1.499,-1.222 ; -1.499,-0.958 -1.499,-0.958 ; -1.499,-0.958 -1.499,-0.958 ; -1.499,-0.958 -1.499,-0.958 ; -1.499,-0.958 -1.499,-0.958 ; -1.499,-0.958 -1.499,-0.958 ; -1.499,-0.958 -1.499,-0.958 ; -1.499,-0.958 -1.499,-0.958 ; -1.499,-0.958 -1.499,-0.958 ; -1.499,-0.958 -1.499,-0.958 ; -1.499,-0.958 -1.499,-0.958 ; -1.499,-0.958 -1.499,-0.959 ; -1.499,-0.958 -1.499,-0.958 ; -1.499,-0.958 -1.499,-0.958 ; -1.499,-0.958 -1.499,-0.958 ; -1.499,-0.958 -1.499,-0.958 ; -1.499,-0.959 -1.499,-0.959 ; -1.499,-0.959 -1.499,-1.222 ; -1.499,-1.222 -1.499,-1.774 ; -1.499,-1.222 -1.499,-1.774 ; -3.499,-1.181 ccw(c-2.007,-0.169) -3.282,-1.444 ccw(c-1.983,-0.144) -2.498,-1.908 ccw(c-1.983,-0.144) -2.345,-1.946 ccw(c-1.983,-0.144) -2.303,-1.954
L_0402 [mm]
  rect 0.65x0.7 smd mask+0.03: 1(0,0) 2(0.9,0)
  silkscreen extent -0.5,-0.5 1.4,0.5
L_0603_JU#1 [mm] "0603 jumper"
  rect 1x1 smd mask+0.05: 1(0,0) 2(0,-1.9)
  silkscreen extent -0.65,-2.5 0.65,0.6, body extent -0.39,-1.74 0.39,-0.14, height 0.89
L_0603_JU#2 [mm] "0603 jumper"
  rect 1x1 smd: 1(0,0) 2(0,-1.9)
  silkscreen extent -0.65,-2.5 0.65,0.6, body extent -0.39,-1.74 0.39,-0.14, height 0.89
"PCBComponent_1 - duplicate" [mm]
  round 1 smd: 1(-1.762,3.53) 2(1.838,2.52)
  Top Layer lines w0.5: 1.344,-3.31 1.337,0.953 ; 1.333,-3.285 cw(c-0.036,0.036) -1.344,-3.31 -1.337,0.953 ; -3.37,-3 -2.178,-3 ; 2.171,-3 3.363,-3 ; -2.941,-2 -2.342,-2 ; -1.351,-2 -2.342,-2 ; 1.351,-2 2.342,-2 ; 2.941,-2 2.342,-2 ; -4.306,-1.328 cw(c-3.565,-2) -3.565,-1 ; 4.299,-1.328 ccw(c3.558,-2) 4.107,-1.164 ccw(c3.558,-2) 3.558,-1 ; -4.44,-1 -3.601,-1 ; -3.598,-1 cw(c-3.598,0) -3.601,-1 ; -2.233,-1 -3.601,-1 ; 2.226,-1 3.558,-1 ; 4.433,-1 4.097,-1 3.592,-1 ; -3.581,0 -2.342,0 ; -1.374,0 -2.342,0 ; 1.374,0 3.581,0 ; 2.342,0 ccw(c2.342,-1) 2.342,-2 ; -2.336,0.001 ccw(c-2.336,1.001) -1.337,0.953 ; 2.336,0.001 cw(c2.336,1.001) 1.337,0.953 ; -4.446,1 -3.603,1 ; -3.598,1 ccw(c-3.598,0) -3.603,1 ; -2.239,1 -3.603,1 ; 2.232,1 3.465,1 3.592,1 ; 4.439,1 3.596,1 ; -4.371,1.36 ccw(c-3.603,2) -3.603,1 ; 4.364,1.36 cw(c3.596,2) 3.596,1 ; 2.853,1.996 ccw(c1.073,1.28) 2.851,2 ; -2.941,2 -2.299,2 ; -1.374,2 -2.299,2 ; -1.335,2 -1.337,1.045 ; 1.374,2 1.775,2 2.184,2 ; 2.863,2 2.851,2 ; -2.336,2.001 cw(c-2.336,1.001) -2.299,2 ; 2.336,2.001 ccw(c2.336,1.001) 2.299,2 ; 1.728,2.35 2.002,2.076 ccw(c2.184,2.259) 2.184,2 ; 1.549,2.737 cw(c1.549,1.819) 1.7,2.725 cw(c1.549,1.819) 1.725,2.72 cw(c1.549,1.819) 2.198,2.468 2.666,2 ; 3.493,2.994 cw(c-0.014,0.017) 4.585,0.114 ; -3.504,3 -3.078,3.001 ; -3.079,3 -3.078,3.001 ; -2.493,3 cw(c-2.123,3) -2.493,3.001 ; -2.153,3 cw(c-1.783,3) -2.153,3.002 ; -1.654,3.042 -1.654,3.615 -1.654,3.994 cw(c-1.428,3.994) -1.588,4.154 ; -1.95,3.356 -2.044,3.262 ccw(c-1.783,3) -2.153,3.002 ; -1.929,3.717 -1.978,3.668 -2.385,3.262 ccw(c-2.123,3) -2.493,3.001 ; -1.854,3.909 ccw(c-1.854,3.148) -2.393,3.686 -3.078,3.001 ; -2.342,-2 ccw(c-2.342,-1) -2.342,0 ; -3.601,-1 cw(c-3.598,0) -3.603,1 ; 3.558,-1 3.592,-1 ; 3.592,-1 ccw(c3.592,0) 4.072,-0.877 ccw(c3.592,0) 4.584,-0.124 ; 4.584,-0.124 ccw(c-0.014,0.017) 4.585,0.114 ; 4.584,-0.124 ccw(c3.592,0) 4.585,0.114 ; 4.584,-0.124 cw(c-0.014,0.017) 4.226,-1.767 cw(c-0.014,0.017) 0.649,-4.535 cw(c-0.014,0.017) -0.677,-4.535 cw(c-0.014,0.017) -1.324,4.426 -1.335,3.003 -2.153,3.002 ; 4.585,0.114 ccw(c3.592,0) 3.596,1 ; -1.337,0.953 ccw(c-2.336,1.001) -1.337,1.045 ; -1.337,0.953 -1.337,1.045 ; -1.337,0.953 -1.337,0.953 ; -1.337,0.953 -1.337,0.953 ; -1.337,0.953 -1.337,0.953 ; -1.337,0.953 -1.337,0.953 ; -1.337,0.953 -1.337,0.953 ; -1.337,0.953 -1.337,0.953 ; -1.337,0.953 -1.337,0.953 ; -1.337,0.953 -1.337,0.953 ; -1.337,0.953 -1.337,0.953 ; -1.337,0.953 -1.337,0.953 ; -1.337,0.953 -1.337,0.953 ; -1.337,0.953 -1.337,0.953 ; -1.337,0.953 -1.337,0.953 ; -1.337,0.953 -1.337,0.953 ; -1.337,0.953 -1.337,0.953 ; -1.337,0.953 -1.337,0.953 ; -1.337,0.953 -1.337,0.953 ; -1.337,0.953 -1.337,0.953 ; -1.337,0.953 -1.337,0.953 ; -1.337,0.953 -1.337,0.953 ; -1.337,0.953 -1.337,0.953 ; -1.337,0.953 -1.337,0.953 ; -1.337,0.953 -1.337,0.953 ; -1.337,0.953 -1.337,0.953 ; -1.337,0.953 -1.337,0.953 ; -1.337,0.953 -1.337,0.953 ; -1.337,0.953 -1.337,0.953 ; -1.337,0.953 -1.337,0.953 ; -1.337,0.953 -1.337,0.953 ; -1.337,0.953 -1.337,0.953 ; 1.337,0.953 cw(c2.336,1.001) 1.337,1.045 ; 1.337,0.953 1.337,1.045 ; 3.592,1 cw(c3.592,0) 3.596,1 ; 3.592,1 3.596,1 ; -1.337,1.045 ccw(c-2.336,1.001) -2.299,2 ; 1.337,1.045 cw(c2.336,1.001) 2.299,2 ; 1.337,1.045 1.335,2 1.335,2.44 1.335,2.49 1.335,3.18 cw(c1.073,1.28) 1.712,3.089 cw(c1.073,1.28) 1.725,3.084 cw(c1.073,1.28) 1.85,3.034 cw(c1.073,1.28) 2,2.96 cw(c1.073,1.28) 2.851,2 ; -2.299,2 -2.299,2 ; -2.299,2 -2.299,2 ; -2.299,2 -2.299,2 ; -2.299,2 -2.299,2 ; -2.299,2 -2.299,2 ; -2.299,2 -2.299,2 ; -2.299,2 -2.299,2 ; -2.299,2 -2.299,2 ; -2.299,2 -2.299,2 ; -2.299,2 -2.299,2 ; -2.299,2 -2.299,2 ; -2.299,2 -2.299,2 ; -2.299,2 -2.299,2 ; -2.299,2 -2.299,2 ; -2.299,2 -2.299,2 ; -2.299,2 -2.299,2 ; -2.299,2 -2.299,2 ; -2.299,2 -2.299,2 ; -2.299,2 -2.299,2 ; -2.299,2 -2.299,2 ; -2.299,2 -2.299,2 ; -2.299,2 -2.299,2 ; -2.299,2 -2.299,2 ; -2.299,2 -2.299,2 ; -2.299,2 -2.299,2 ; -2.299,2 -2.299,2 ; -2.299,2 -2.299,2 ; -2.299,2 -2.299,2 ; -2.299,2 -2.299,2 ; -2.299,2 -2.299,2 ; -2.299,2 -2.299,2 ; 2.184,2 ccw(c2.184,2.259) 2.184,2 ; 2.184,2 2.184,2 ; 2.184,2 2.299,2 ; 2.299,2 2.666,2 ; 2.299,2 2.299,2 ; 2.299,2 2.299,2 ; 2.299,2 2.299,2 ; 2.299,2 2.299,2 ; 2.299,2 2.299,2 ; 2.299,2 2.299,2 ; 2.299,2 2.299,2 ; 2.299,2 2.299,2 ; 2.299,2 2.299,2 ; 2.299,2 2.299,2 ; 2.299,2 2.299,2 ; 2.299,2 2.299,2 ; 2.299,2 2.299,2 ; 2.299,2 2.299,2 ; 2.299,2 2.299,2 ; 2.299,2 2.299,2 ; 2.299,2 2.299,2 ; 2.299,2 2.299,2 ; 2.299,2 2.299,2 ; 2.299,2 2.299,2 ; 2.299,2 2.299,2 ; 2.299,2 2.299,2 ; 2.299,2 2.299,2 ; 2.299,2 2.299,2 ; 2.299,2 2.299,2 ; 2.299,2 2.299,2 ; 2.299,2 2.299,2 ; 2.299,2 2.299,2 ; 2.299,2 2.299,2 ; 2.299,2 2.299,2 ; 2.299,2 2.299,2 ; 2.666,2 2.851,2 ; -3.078,3.001 -2.493,3.001 ; -2.493,3.001 -2.153,3.002
R_0402#1 [mm]
  rect 0.65x0.75 smd mask+0.03: 1(0,0) 2(1,0)
  silkscreen extent -0.5,-0.55 1.5,0.55
R_0402#2 [mm]
  rect 0.65x0.75 smd: 1(0,0) 2(1,0)
  silkscreen extent -0.5,-0.55 1.5,0.55
R_0603 [mm]
  rect 0.9x0.95 smd: 1(-0.7,0) 2(0.7,0)
  silkscreen extent -1.44,-0.75 1.44,0.75
R_0805_JU [mm] "Resistor Jumper 0805"
  rect 0.9x1.2 smd: 1(0,0) 2(2.3,0)
  silkscreen extent -1,-1.1 3.3,1.1, body extent 0.15,-0.6 2.15,0.6, height 1.02
R_1206_JU [mm]
  rect 1.3x1.5 smd: 1(0,0) 2(3.1,0)
  silkscreen extent -1,-1.1 4.1,1.1
R_1812_JU [mm] "1812 jumper"
  rect 1.3x3.2 smd: 1(0,0) 2(4.5,0)
  silkscreen extent -1,-2 5.5,2
R_2010_JU#1 [mm]
  rect 1.4x2.4 smd: 1(0,0) 2(4.7,0)
  silkscreen extent -1,-1.5 5.7,1.5
R_2010_JU#2 [mm]
  rect 1.4x2.4 smd mask+0: 1(0,0) 2(4.7,0)
  silkscreen extent -1,-1.5 5.7,1.5
R_2512_JU [mm]
  rect 1.4x3 smd: 1(0,0) 2(6,0)
  silkscreen extent -1,-1.75 7,1.75
SMDPN [mm]
  rect 0.9x0.95 smd: 1(-0.008,0) 2(1.872,0) 3(0.942,2.35)
  silkscreen extent -0.4,-0.53 2.34,2.8
SOT23-5 [mm]
  rect 0.55x1.45 smd: 1(-0.95,-1.075) 2(0,-1.075) 3(0.95,-1.075) 4(0.95,1.075) 5(-0.95,1.075)
  silkscreen extent -1.68,-2.22 1.55,0.9
USP-3 [mm]
  rect 0.35x0.4 smd mask+0.03: 1(0.3,0.55) 2(-0.3,0.55)
  rect 0.5x0.3 smd: 3(-0.65,-0.25) 3(0.65,-0.25)
  rect 1x0.6 smd: 3(0,-0.25)
  silkscreen extent -0.6,-0.7 0.6,0.5

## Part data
AT1: library part ANT_DIFF_DIPOLE_RF4CE_REMOTE
BAT1: library part BATT_AA, "Battery Holder Dual Cell"
C1 C3 C19 C20: library part 550-1043-016
C2: library part 550-0021-000
C4: library part 550-0022-000
C5 C13 C17: library part 550-1032-025
C9: library part 550-0048-000
C10 C11: library part 550-0046-000
C14 C15: library part 550-2201-050
C16 C22: library part 550-1001-050
C18: library part 550-474A-010
C21: library part EMBER_CAPACITOR.1_1
C23: library part 550-0043-000
C24: library part 550-0047-000
D1 D2 D3: library part EMBER_LED, "*"
J1: library part 610_0045_000_HEADER_10P_D_050.1_1, "InSight Port"
JP1 JP10: library part TraceJumper_0603
JP2 JP4 JP5 JP8 JP9 JP12 JP13 JP20: library part TraceJumper_2010
JP3: library part TraceJumper_0805
JP6 JP7: library part TraceJumper_2512
JP17: library part TraceJumper_1206
L1: library part 566-0083-000, "Design Placeholder"
L2: library part 566-3N3M-000, "Design Placeholder"
PCB1: library part 710-0664-003, "PCB BoM ID and Top Side Silk Screen Identifier"
Q1: library part Transistor, "Transistor"
Q2 Q3: library part MOSFET_N-Channel, "MOSFET N-Channel"
R1 R9 R10 R11 R12 R13: library part 555-0000-TBD
R2: library part 555-1R05-016
U1: library part 540-0341-000, "IC, EM357, ZIGBEE/802.15.4 RF SOLUTION, ARM CORTEX-M3, 12K RAM, 192K FLASH, QFN-48"
U2: library part AND_GATE
Y1: library part HC49_TH, "OSCILLATOR, CRYSTAL, 24.000MHZ, 18PF LOAD, +/-10PPM TOLERANCE, +/-25PPM STABILITY, -40C TO 85C, AT49"

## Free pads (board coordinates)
  round 1.524 / inner round 1.524 / far side round 0 hole 0.8: 0(2.2,4.975) 1(2.2,-4.95)
  round 1.524 / inner round 1.524 / far side round 0 hole 0.762: 0(120.57,-3.91) 0(139.82,21.6) 0(163.4,22.55) 0(166.58,-5.84) 0(181.04,21.55) 1(137.15,-10.07) 2(144.3,21.22) 3(147.31,21.37) 3(150.04,21.35) 3(151.54,6.06) 4(142.77,1.04) 5(108.25,-8.99) 7(128.05,19.93) 8(162.9,-14.03)
  oval 1.524x4 smd: 2(2.2,-4.95)
  round 0.8 hole 0.8: 22(201.075,-13.5) 23(201.3,-13.5) 24(201.5,-13.5) 25(201.775,-13.5) 26(202,-13.5) 27(202.3,-13.5) 28(202.6,-13.5) 29(202.875,-13.5) 30(203.025,-13.5) 31(203.15,-13.5) 32(203.275,-13.5) 33(203.35,-13.5) 34(203.425,-13.5) 35(203.475,-13.5) 36(203.55,-13.5) 37(203.65,-13.5) 38(203.775,-13.5) 39(203.875,-13.5) 40(203.975,-13.5) 41(201.2,-13.5) 42(201.375,-13.5) 43(201.6,-13.5) 44(201.775,-13.5) 45(201.925,-13.5) 46(202.1,-13.5) 47(202.3,-13.5) 48(202.425,-13.5) 49(202.25,-13.5) 50(202.75,-13.5) 51(201.05,13.575) 52(203.925,13.575) 53(203.8,13.575) 54(203.7,13.575) 55(203.575,13.575) 56(203.525,13.575) 57(203.45,13.575) 58(203.4,13.575) 59(203.3,13.575) 60(203.225,13.575) 61(203.125,13.575) 62(202.95,13.575) 63(202.8,13.575) 64(202.775,13.575) 65(202.7,13.575) 66(202.65,13.575) 67(202.55,13.575) 68(202.475,13.575) 69(202.4,13.575) 70(202.325,13.575) 71(202.25,13.575) 72(202.2,13.575) 73(202.075,13.575) 74(202.025,13.575) 75(201.925,13.575) 76(201.875,13.575) 77(201.75,13.575) 78(201.75,13.575) 79(201.7,13.575) 80(201.675,13.575) 81(201.6,13.575) 82(201.575,13.575) 83(201.5,13.575) 84(201.425,13.575) 85(201.325,13.575) 86(201.25,13.575) 87(201.2,13.575) 88(201.15,13.575)

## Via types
v1: diameter 1.2, hole 0, Top Layer to Carbon Ink Layer, 80 vias

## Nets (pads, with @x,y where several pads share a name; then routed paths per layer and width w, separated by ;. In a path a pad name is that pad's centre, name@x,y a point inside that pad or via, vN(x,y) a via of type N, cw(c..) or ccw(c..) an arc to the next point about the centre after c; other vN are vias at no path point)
1V8: C5.1 JP1.1 JP2.2 U1.10 | length 11.9
  Top Layer w0.292: U1.10@187.703,-10.6 187.703,-11.038 ccw(c188.257,-11.038) 187.866,-11.429 188.236,-11.8 188.278,-11.8 C5.1@188.594,-12.117 ; 188.391,-11.913 cw(c187.907,-12.397) 188.591,-12.397 ccw(c187.81,-12.397) 188.488,-12.008 ; C5.1@188.622,-12.104 cw(c188.319,-12.408) C5.1@188.747,-12.408 ; C5.1@188.745,-12.422 cw(c188.745,-12.858) 189.053,-12.55 cw(c189.053,-12.813) 189.239,-12.627 cw(c187.541,-14.325) JP1.1@189.943,-14.325 ; JP1.1@189.93,-14.827 cw(c189.93,-15.681) 190.534,-15.077 cw(c191.138,-14.473) JP1.1@190.284,-14.473 ; JP1.1@189.93,-14.473 190.841,-15.384 ccw(c192.637,-13.587) 192.637,-16.127 JP2.2@194.358,-16.127
1V8_1: C13.1 JP3.2 U1.1 U1.2 | length 15.2
  Top Layer w0.292: JP3.2@178.385,-14.02 cw(c177.843,-14.562) 178.61,-14.562 ; 178.61,-14.687 cw(c179.552,-14.687) JP3.2@178.886,-14.02 ; JP3.2@178.66,-13.745 ccw(c178.781,-13.866) 178.61,-13.866 178.61,-15.467 ccw(c179.523,-15.467) 178.878,-16.113 ccw(c179.71,-15.28) 179.71,-16.457 180.533,-16.457 ccw(c180.533,-15.86) 180.955,-16.282 ccw(c180.49,-15.818) 181.147,-15.818 181.147,-13.309 cw(c182.027,-13.309) 181.405,-12.688 cw(c181.597,-12.88) 181.597,-12.608 ; U1.2@183.703,-10.6 183.21,-10.6 183.203,-10.593 cw(c181.567,-10.593) 182.723,-11.749 181.998,-12.475 ccw(c182.13,-12.608) 181.943,-12.608 181.597,-12.608 ; 181.597,-12.608 ccw(c181.597,-12.3) 181.884,-12.412 cw(c181.597,-12.3) 181.597,-12.608 ; C13.1@182.028,-12.264 ccw(c182.028,-11.826) 182.337,-12.135 cw(c182.028,-11.826) C13.1@182.028,-12.264 ; C13.1@182.181,-12.417 cw(c182.487,-12.417) 182.271,-12.202 ccw(c182.487,-12.417) C13.1@182.181,-12.417
1V8_2: C16.1 JP3.1 JP5.1 U1.45 U1.46 | length 16.3
  Top Layer w0.305: JP3.1@178.66,-11.863 178.643,-11.863 cw(c179.035,-11.47) 178.48,-11.47 178.48,-11.203 ; C16.1@178.938,-9.088 C16.1@178.942,-9.092 ; C16.1@179.17,-9.07 C16.1@179.078,-9.07 ; U1.45@182.533,-8.425 182.528,-8.429 U1.46@182.528,-8.925 180.918,-8.925 ccw(c180.918,-9.386) 180.592,-9.06 179.102,-9.06 ccw(c179.102,-9.094) C16.1@179.078,-9.07 ; 178.48,-11.203 cw(c178.131,-11.203) 178.334,-11.487 ccw(c178.131,-11.203) 178.48,-11.203 ; 178.48,-11.203 ccw(c178.732,-11.203) 178.65,-11.442 cw(c178.732,-11.203) 178.48,-11.203 ; 178.48,-11.203 ccw(c178.104,-11.203) 178.37,-10.937 ccw(c176.752,-10.937) 177.896,-9.794 177.799,-9.696 ccw(c177.12,-10.375) JP5.1@177.12,-9.415 ccw(c177.12,-8.413) 177.828,-9.122 cw(c177.953,-9.246) 177.953,-9.07 C16.1@179.078,-9.07 ; C16.1@179.077,-9.07 ccw(c179.077,-10.159) 178.108,-9.664 cw(c179.077,-10.159) C16.1@179.077,-9.07 ; JP5.1@177.836,-9.525 cw(c178.58,-9.905) 178.58,-9.07 ccw(c178.58,-9.905) JP5.1@177.836,-9.525 ; 178.645,-9.07 ccw(c178.645,-8.577) 178.993,-8.926 cw(c178.645,-8.577) 178.645,-9.07 ; C16.1@179.202,-8.926 ccw(c179.526,-8.602) 179.526,-9.06 cw(c179.526,-8.602) C16.1@179.202,-8.926
1V8_3: C9.1 C22.1 JP1.2 L1.2 U1.5 U1.8 | length 24.4
  Top Layer w0.292: U1.5@185.203,-10.6 185.203,-11.069 ccw(c185.661,-11.069) 185.338,-11.392 ccw(c185.73,-11) 185.73,-11.555 186.653,-11.555 ; L1.2@185.898,-13.389 185.931,-13.423 C22.1@186.878,-13.423 ; U1.8@186.703,-10.6 186.703,-12.131 ; C9.1@186.738,-12.395 ccw(c186.549,-12.286) 186.703,-12.131 ; JP1.2@187.988,-14.485 187.235,-14.485 ; L1.2@186.05,-13.516 cw(c186.275,-13.741) 186.275,-13.423 ; L1.2@186.05,-13.516 cw(c186.275,-13.741) 186.275,-13.423 ; L1.2@186.05,-13.516 cw(c186.275,-13.741) 186.275,-13.423 ; L1.2@186.05,-13.263 ccw(c186.435,-12.877) 186.435,-13.423 ; L1.2@186.05,-13.263 ccw(c186.435,-12.877) 186.435,-13.423 ; L1.2@186.05,-13.263 ccw(c186.435,-12.877) 186.435,-13.423 ; 186.383,-13.423 ccw(c186.383,-12.885) C22.1@186.763,-13.265 ; 186.383,-13.423 ccw(c186.383,-12.885) C22.1@186.763,-13.265 ; 186.383,-13.423 ccw(c186.383,-12.885) C22.1@186.763,-13.265 ; 186.703,-12.131 ccw(c186.891,-12.131) C9.1@186.88,-12.318 ; 186.703,-12.131 ccw(c186.891,-12.131) C9.1@186.88,-12.318 ; 186.703,-12.131 ccw(c186.891,-12.131) C9.1@186.88,-12.318 ; 186.703,-12.131 186.915,-12.343 186.915,-12.455 186.925,-12.465 186.925,-12.472 186.925,-14.175 187.235,-14.485 ; 186.703,-11.694 ccw(c187.65,-11.694) C9.1@186.981,-12.363 ; 186.703,-11.694 ccw(c187.65,-11.694) C9.1@186.981,-12.363 ; 186.703,-11.694 ccw(c187.65,-11.694) C9.1@186.981,-12.363 ; C22.1@186.813,-13.483 cw(c186.542,-13.754) 186.925,-13.754 ; C22.1@186.813,-13.483 cw(c186.542,-13.754) 186.925,-13.754 ; C22.1@186.813,-13.483 cw(c186.542,-13.754) 186.925,-13.754 ; C22.1@186.813,-13.265 ccw(c186.542,-12.994) 186.925,-12.994 ; C22.1@186.813,-13.265 ccw(c186.542,-12.994) 186.925,-12.994 ; C22.1@186.813,-13.265 ccw(c186.542,-12.994) 186.925,-12.994 ; C9.1@186.813,-12.581 cw(c186.542,-12.851) 186.925,-12.851 ; C9.1@186.813,-12.581 cw(c186.542,-12.851) 186.925,-12.851 ; C9.1@186.813,-12.581 cw(c186.542,-12.851) 186.925,-12.851 ; 186.925,-13.737 cw(c187.285,-13.737) C22.1@187.03,-13.483 ; 186.925,-13.737 cw(c187.285,-13.737) C22.1@187.03,-13.483 ; 186.925,-13.737 cw(c187.285,-13.737) C22.1@187.03,-13.483 ; 186.925,-13.011 ccw(c187.285,-13.011) C22.1@187.03,-13.265 ; 186.925,-13.011 ccw(c187.285,-13.011) C22.1@187.03,-13.265 ; 186.925,-13.011 ccw(c187.285,-13.011) C22.1@187.03,-13.265 ; 186.925,-12.836 cw(c187.285,-12.836) C9.1@187.031,-12.581 ; 186.925,-12.836 cw(c187.285,-12.836) C9.1@187.031,-12.581 ; 186.925,-12.836 cw(c187.285,-12.836) C9.1@187.031,-12.581 ; 187.235,-14.485 cw(c187.235,-15.226) JP1.2@187.773,-14.716 ; 187.235,-14.485 ccw(c187.235,-13.793) JP1.2@187.761,-14.243 ; 187.235,-14.485 cw(c187.235,-15.226) JP1.2@187.773,-14.716 ; 187.235,-14.485 ccw(c187.235,-13.793) JP1.2@187.761,-14.243 ; 187.235,-14.485 ccw(c187.235,-13.793) JP1.2@187.761,-14.243 ; 187.235,-14.485 cw(c187.235,-15.226) JP1.2@187.773,-14.716 ; 186.617,-12.045 cw(c186.33,-12.331) 186.723,-12.433 ccw(c186.33,-12.331) 186.617,-12.045
1V8_4: JP2.1 JP13.2 R2.1 U1.15 | length 123
  Top Layer w0.254: JP2.1@193.425,-11.45 193.615,-11.26 cw(c194.545,-12.191) 194.545,-10.875 ccw(c194.545,-10.217) 195.01,-10.682 195.218,-10.475 ccw(c194.598,-9.856) 195.474,-9.856 195.474,-4.825 ; 194.202,6.306 cw(c193.422,5.526) 194.525,5.526 194.525,-1.926 ccw(c196.346,-1.926) 195.058,-3.214 cw(c194.052,-4.221) 195.475,-4.221 195.475,-4.832
  Top Layer w0.292: U1.15@189.378,-8.925 190.204,-8.925 cw(c190.204,-9.356) 190.509,-9.051 190.632,-9.174 cw(c189.965,-9.84) R2.1@190.907,-9.84
  Top Layer w0.508: 181.672,15.225 ccw(c182.528,16.081) 182.528,14.87 184.585,14.87 cw(c184.585,12.33) 186.381,14.127 194.202,6.306 ; R2.1@191.03,-9.881 cw(c190.884,-10.027) 191.04,-9.891 cw(c190.884,-10.027) 191.091,-10.027 191.091,-10.156 ccw(c191.902,-10.156) 191.328,-10.729 ccw(c192.965,-9.092) 192.965,-11.408 JP2.1@193.44,-11.408
  Top Layer w0.635: JP13.2@131.56,11.36 JP13.2@132.15,11.36 ; JP13.2@132.925,10.934 cw(c133.93,9.961) 133.93,11.36 ; 152.988,15.778 180.337,15.778 cw(c180.337,13.89) 181.672,15.225 ; 153.242,15.93 153.322,16.01 181.1,16.01 181.72,15.39
  Top Layer w0.8: JP13.2@132.15,11.2 133.77,11.2 136.69,14.12 151.432,14.12 153.242,15.93
1V8_5: JP5.2 JP12.1 R1.1 | length 71.9
  Top Layer w0.635: JP12.1@127.68,-16.73 JP12.1@128.65,-16.73 ; JP12.1@129.27,-17.095 cw(c130.153,-17.978) 130.153,-16.73 ; JP12.1@129.27,-16.555 ccw(c129.694,-16.131) 129.694,-16.73 ; 150.32,-16.73 152.72,-14.33 159.95,-14.33 161.83,-12.45 170.027,-12.45 ccw(c170.027,-9.787) 171.91,-11.67 ccw(c170.174,-9.934) 172.629,-9.934 172.629,-8.641 cw(c175.695,-8.641) 173.527,-6.473 174.354,-5.646 cw(c176.523,-7.814) 176.523,-4.747 JP5.2@177.228,-4.747 ; 161.9,-12.56 171.16,-12.56 172.493,-11.227 ; 172.58,-11.08 172.58,-10.526 ; JP5.2@176.187,-4.933 cw(c176.33,-7.996) 176.33,-4.93 JP5.2@177.16,-4.93 ; JP5.2@177.705,-4.747 cw(c178.966,-6.009) 178.966,-4.225 R1.1@179.205,-4.225
  Top Layer w0.8: JP12.1@128.65,-16.73 150.32,-16.73
1V8_6: JP13.1 JP19.2 | length 8.8
  Top Layer w0.8: JP19.2@131.07,1.42 128.91,3.58 128.91,5.85 129.56,6.5 JP13.1@132.15,6.5
1V8_7: JP19.1 JP20.2 | length 4.4
  Top Layer w1: JP19.1@131.175,-1.725 131.175,-2.055 133.03,-3.91 JP20.2@133.03,-5.39
1V8_8: JP12.2 JP20.1 | length 6
  Top Layer w1: JP12.2@128.5,-12.125 131.975,-12.125 133.1,-11 JP20.1@133.1,-10.08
